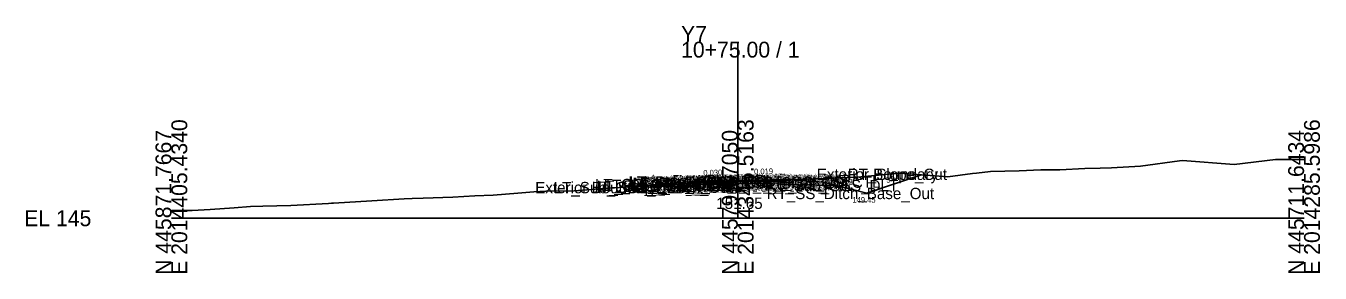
# Model space of a CAD drawing. Extents: x -26 to 203, y -10 to 7527.
# Drawn here: x -25.7 to 202.8, y 1490.3 to 1534 of the extents above; entities that cross this region are included whole.
import ezdxf

# ---------------------------------------------------------------- set-up
doc = ezdxf.new("R2010")
doc.units = 0
for name, color, linetype in [('Exist CMT Pavement', 7, 'Continuous'), ('Exist Cross Section Cell', 7, 'Continuous'), ('Exist XS Center Line Elevation Label', 7, 'Continuous'), ('Exist XS Ground Line', 7, 'Continuous'), ('Prop CMT Pvmt Course 1', 7, 'Continuous'), ('Prop CMT Pvmt Course 1 Wedge', 7, 'Continuous'), ('Prop CMT Pvmt Course 2', 7, 'Continuous'), ('Prop CMT Pvmt Course 2 Wedge', 7, 'Continuous'), ('Prop CMT Pvmt Course 3', 7, 'Continuous'), ('Prop CMT Pvmt Course 3 Wedge', 7, 'Continuous'), ('Prop CMT Pvmt Surface', 7, 'Continuous'), ('Prop CMT Pvmt Surface Shoulder', 7, 'Continuous'), ('Prop CMT Pvmt Wedge Surface 1', 7, 'Continuous'), ('Prop CMT Pvmt Wedge Surface 2', 7, 'Continuous'), ('Prop CMT Pvmt Wedge Surface 3', 7, 'Continuous'), ('Prop CMT Shld Paved Course 1', 7, 'Continuous'), ('Prop CMT Shld Paved Course 2', 7, 'Continuous'), ('Prop CMT Shld Paved Course 3', 7, 'Continuous'), ('Prop CMT Slope Grass', 7, 'Continuous'), ('Prop CMT Subgrade Earthwork', 7, 'Continuous'), ('Prop XS Ditch Standard Text', 7, 'Continuous'), ('Prop XS Earthwork Shape', 7, 'Continuous'), ('Prop XS SE Text', 7, 'Continuous'), ('Prop XS Side Slope Text', 7, 'Continuous'), ('Scratch_Level_0', 7, 'Continuous')]:
    doc.layers.add(name, color=color, linetype=linetype)

msp = doc.modelspace()

# ---------------------------------------------------------------- linework, layer by layer
at = {"layer": 'Exist CMT Pavement'}
msp.add_lwpolyline([(93.34, 1506.4), (94.16, 1506.44), (100, 1506.65), (101.02, 1506.69), (101.74, 1506.69), (107.53, 1506.71)], dxfattribs=at)
at = {"layer": 'Exist Cross Section Cell'}
for p, q in [((100, 1500), (100, 1531.19)), ((0, 1500), (100, 1500)), ((100, 1500), (200, 1500))]:
    msp.add_line(p, q, dxfattribs=at)
at = {"layer": 'Exist XS Ground Line'}
msp.add_lwpolyline([(0, 1501.37), (3.64, 1501.37), (6.82, 1501.53), (11.08, 1501.85), (13.97, 1502.09), (16.13, 1502.15), (21.11, 1502.26), (27.77, 1502.63), (28.26, 1502.66), (28.62, 1502.68), (35.4, 1503.07), (41.11, 1503.42), (42.54, 1503.52), (44.46, 1503.56), (49.69, 1503.7), (53.6, 1503.94), (56.83, 1504.1), (61.15, 1504.46), (63.98, 1504.65), (66.09, 1504.77), (71.12, 1504.87), (77.84, 1505.37), (78.27, 1505.38), (79.84, 1505.49), (90.97, 1506.09), (93.34, 1506.4), (94.16, 1506.44), (100, 1506.65), (101.02, 1506.69), (101.74, 1506.69), (107.53, 1506.71), (108.47, 1506.86), (112, 1506.89), (121.14, 1507.27), (127.92, 1507.91), (128.55, 1507.94), (137.08, 1507.31), (141.47, 1507.88), (142.19, 1507.95), (144.61, 1508.25), (149.72, 1508.37), (153.54, 1508.58), (156.86, 1508.58), (161.3, 1508.8), (164.01, 1508.84), (166.03, 1508.88), (171.15, 1509.2), (177.99, 1510.15), (178.52, 1510.19), (187.64, 1509.52), (194.94, 1510.4), (200, 1510.37)], dxfattribs=at)
at = {"layer": 'Prop CMT Pvmt Course 1'}
for points in [[(100, 1506.69), (91.43, 1506.44)], [(91.43, 1506.44), (91.43, 1506.19)], [(91.43, 1506.19), (93.34, 1506.24)], [(93.34, 1506.37), (100, 1506.57)], [(93.34, 1506.24), (93.34, 1506.37)], [(100, 1506.69), (109.07, 1506.86)], [(107.53, 1506.71), (100, 1506.57)], [(100, 1506.44), (100, 1506.69)], [(100, 1506.44), (100, 1506.69)], [(100, 1506.57), (100, 1506.44), (100, 1506.44)], [(100, 1506.57), (100, 1506.44), (100, 1506.44)], [(107.53, 1506.58), (107.53, 1506.71)], [(109.07, 1506.61), (107.53, 1506.58)], [(109.07, 1506.86), (109.07, 1506.61)]]:
    msp.add_lwpolyline(points, dxfattribs=at)
at = {"layer": 'Prop CMT Pvmt Course 1 Wedge'}
for points in [[(100, 1506.57), (93.34, 1506.37)], [(100, 1506.57), (107.53, 1506.71)]]:
    msp.add_lwpolyline(points, dxfattribs=at)
at = {"layer": 'Prop CMT Pvmt Course 2'}
for points in [[(93.34, 1506.24), (91.43, 1506.19)], [(91.43, 1506.19), (91.43, 1505.85)], [(93.34, 1505.91), (93.34, 1506.24)], [(107.53, 1506.58), (109.07, 1506.61)], [(107.53, 1506.25), (107.53, 1506.58)], [(109.07, 1506.28), (107.53, 1506.25)], [(109.07, 1506.61), (109.07, 1506.28)], [(91.43, 1505.85), (93.34, 1505.91)]]:
    msp.add_lwpolyline(points, dxfattribs=at)
at = {"layer": 'Prop CMT Pvmt Course 2 Wedge'}
for points in [[(100, 1506.44), (93.34, 1506.24)], [(100, 1506.44), (107.53, 1506.58)]]:
    msp.add_lwpolyline(points, dxfattribs=at)
at = {"layer": 'Prop CMT Pvmt Course 3'}
for points in [[(107.53, 1506.25), (109.07, 1506.28)], [(107.53, 1505.92), (107.53, 1506.25)], [(109.07, 1506.28), (109.07, 1505.94)], [(93.34, 1505.91), (91.43, 1505.85)], [(91.43, 1505.85), (91.43, 1505.52)], [(91.43, 1505.52), (93.34, 1505.58)], [(93.34, 1505.58), (93.34, 1505.91)], [(109.07, 1505.94), (107.53, 1505.92)]]:
    msp.add_lwpolyline(points, dxfattribs=at)
at = {"layer": 'Prop CMT Pvmt Course 3 Wedge'}
for points in [[(100, 1506.11), (93.34, 1505.91)], [(100, 1506.11), (107.53, 1506.25)]]:
    msp.add_lwpolyline(points, dxfattribs=at)
at = {"layer": 'Prop CMT Pvmt Surface'}
for points in [[(100, 1506.69), (91.43, 1506.44)], [(100, 1506.69), (109.07, 1506.86)]]:
    msp.add_lwpolyline(points, dxfattribs=at)
at = {"layer": 'Prop CMT Pvmt Surface Shoulder'}
for points in [[(91.43, 1506.44), (91.43, 1506.44)], [(109.07, 1506.86), (109.07, 1506.86)]]:
    msp.add_lwpolyline(points, dxfattribs=at)
at = {"layer": 'Prop CMT Pvmt Wedge Surface 1'}
for points in [[(91.43, 1506.19), (91.43, 1506.44)], [(93.34, 1506.24), (91.43, 1506.19)], [(100, 1506.57), (93.34, 1506.37)], [(93.34, 1506.37), (93.34, 1506.24)], [(100, 1506.57), (107.53, 1506.71)], [(107.53, 1506.71), (107.53, 1506.58)], [(107.53, 1506.58), (109.07, 1506.61)], [(109.07, 1506.61), (109.07, 1506.86)]]:
    msp.add_lwpolyline(points, dxfattribs=at)
at = {"layer": 'Prop CMT Pvmt Wedge Surface 2'}
for points in [[(100, 1506.44), (91.43, 1506.19)], [(91.43, 1506.19), (91.43, 1506.44)], [(100, 1506.44), (109.07, 1506.61)], [(109.07, 1506.61), (109.07, 1506.86)]]:
    msp.add_lwpolyline(points, dxfattribs=at)
at = {"layer": 'Prop CMT Pvmt Wedge Surface 3'}
for points in [[(91.43, 1505.85), (91.43, 1506.44)], [(100, 1506.11), (91.43, 1505.85)], [(100, 1506.11), (109.07, 1506.28)], [(109.07, 1506.28), (109.07, 1506.86)]]:
    msp.add_lwpolyline(points, dxfattribs=at)
at = {"layer": 'Prop CMT Shld Paved Course 1'}
for points in [[(91.43, 1506.44), (91.18, 1506.18)], [(91.18, 1506.18), (91.43, 1506.19)], [(91.43, 1506.44), (91.43, 1506.44)], [(91.43, 1506.19), (91.43, 1506.44)], [(109.07, 1506.86), (109.07, 1506.86)], [(109.07, 1506.86), (109.33, 1506.61)], [(109.07, 1506.61), (109.07, 1506.86)], [(109.33, 1506.61), (109.07, 1506.61)]]:
    msp.add_lwpolyline(points, dxfattribs=at)
at = {"layer": 'Prop CMT Shld Paved Course 2'}
for points in [[(91.43, 1506.19), (91.18, 1506.18), (90.84, 1505.84)], [(91.43, 1505.85), (91.43, 1506.19)], [(109.07, 1506.61), (109.33, 1506.61), (109.67, 1506.27)], [(109.07, 1506.28), (109.07, 1506.61)], [(109.67, 1506.27), (109.07, 1506.28)], [(90.84, 1505.84), (91.43, 1505.85)]]:
    msp.add_lwpolyline(points, dxfattribs=at)
at = {"layer": 'Prop CMT Shld Paved Course 3'}
for points in [[(109.07, 1506.28), (109.17, 1506.28), (109.67, 1506.27), (110.01, 1505.93)], [(109.07, 1505.94), (109.07, 1506.28)], [(90, 1505.49), (91.43, 1505.52)], [(91.43, 1505.85), (90.84, 1505.84), (90.5, 1505.5)], [(91.43, 1505.52), (91.43, 1505.85)], [(110.51, 1505.92), (109.07, 1505.94)]]:
    msp.add_lwpolyline(points, dxfattribs=at)
at = {"layer": 'Prop CMT Slope Grass'}
for points in [[(91.43, 1506.44), (85.43, 1505.96), (84.85, 1505.76)], [(109.07, 1506.86), (115.07, 1506.38), (122.79, 1504.45)], [(122.79, 1504.45), (132.4, 1507.66)]]:
    msp.add_lwpolyline(points, dxfattribs=at)
at = {"layer": 'Prop CMT Subgrade Earthwork'}
msp.add_line((90, 1505.49), (84.85, 1505.76), dxfattribs=at)
for points in [[(93.34, 1505.58), (93.34, 1506.4)], [(107.53, 1505.92), (107.53, 1506.71)], [(91.43, 1505.52), (90, 1505.49)], [(93.34, 1505.58), (91.43, 1505.52)], [(107.53, 1505.92), (109.07, 1505.94)], [(109.07, 1505.94), (110.51, 1505.92)], [(110.51, 1505.92), (117.49, 1505.78)]]:
    msp.add_lwpolyline(points, dxfattribs=at)
at = {"layer": 'Prop XS Earthwork Shape'}
for points in [[(84.85, 1505.76), (90.97, 1506.09), (93.34, 1506.4), (93.34, 1505.58), (91.43, 1505.52), (90, 1505.49)], [(108.43, 1506.85), (109.07, 1506.86), (115.07, 1506.38), (117.49, 1505.78), (110.51, 1505.92), (109.07, 1505.94), (107.53, 1505.92), (107.53, 1506.71)], [(108.43, 1506.85), (108.47, 1506.86), (112, 1506.89), (121.14, 1507.27), (127.92, 1507.91), (128.55, 1507.94), (132.4, 1507.66), (122.79, 1504.45), (117.49, 1505.78), (115.07, 1506.38), (109.07, 1506.86)]]:
    msp.add_lwpolyline(points, close=True, dxfattribs=at)

# ---------------------------------------------------------------- texts
at = {"layer": 'Exist Cross Section Cell'}
for s, p in [('Y7', (90, 1531.19)), ('10+75.00 / 1', (90, 1528.39)), ('EL 145', (-26, 1498.6))]:
    msp.add_text(s, height=2.8, dxfattribs=at).set_placement(p)
for s, p in [('N 445871.7667', (0, 1490)), ('E 2014405.4340', (2.8, 1490)), ('N 445791.7050', (100, 1490)), ('E 2014345.5163', (102.8, 1490)), ('N 445711.6434', (200, 1490)), ('E 2014285.5986', (202.8, 1490))]:
    msp.add_text(s, height=2.8, rotation=90, dxfattribs=at).set_placement(p)
at = {"layer": 'Exist XS Center Line Elevation Label'}
msp.add_text('151.65', height=2, dxfattribs=at).set_placement((96.22, 1501.65))
at = {"layer": 'Prop XS Ditch Standard Text'}
msp.add_text('149.45', height=1, dxfattribs=at).set_placement((120.25, 1502.74))
at = {"layer": 'Prop XS SE Text'}
for s, rotation, p in [('0.030', 1.7184, (93.94, 1507.51)), ('0.019', 1.0645, (102.9, 1507.75))]:
    msp.add_text(s, height=1, rotation=rotation, dxfattribs=at).set_placement(p)
at = {"layer": 'Prop XS Side Slope Text'}
for s, rotation, p in [('3:1', 18.4332, (84.01, 1506.27)), ('4:1', 345.9638, (118.49, 1506.3)), ('3:1', 18.4349, (126.35, 1506.18))]:
    msp.add_text(s, height=1, rotation=rotation, dxfattribs=at).set_placement(p)
at = {"layer": 'Scratch_Level_0'}
for s, p in [('Exterior Boundary', (113.97, 1506.76)), ('RT_Slope_Cut', (119.42, 1506.76)), ('Exterior Boundary', (64.25, 1504.42)), ('LT_Sub_OSS_DLT', (67.51, 1504.42)), ('LT_Sub_Trench_Out', (74.2, 1504.49)), ('LT_GS_OS_CTL', (74.8, 1504.96)), ('LT_Slope_Fill', (75.09, 1504.67)), ('LT_PS3_Shelf_Out', (76.32, 1504.83)), ('LT_Sub Tie Out', (80.68, 1505.4)), ('LT_PV_OEEOP_EG', (80.89, 1505.4)), ('LT_PS3_OEOP', (81.08, 1504.84)), ('LT_PS2_OEOP', (81.42, 1505.18)), ('LT_Sub_OEOT', (81.51, 1504.52)), ('LT_PV2_OEOT', (81.61, 1505.19)), ('LT_PV3_OEOT', (81.61, 1504.85)), ('LT_PV1_OEOT', (82.17, 1505.44)), ('LT_PS1_OEOP', (82.24, 1505.44)), ('LT_Sub_OEEOP', (82.55, 1504.58)), ('LT_PV2_OEEOP', (82.65, 1505.24)), ('LT_PV3_OEEOP', (82.65, 1504.91)), ('LT_PV1_OEEOP', (83.22, 1505.37)), ('RT_PV_IEEOP_EG', (88.14, 1505.65)), ('LT_PV_IEEOP_EG', (88.19, 1505.65)), ('RT_PV2_IEEOP', (89.91, 1505.44)), ('RT_PV3_IEEOP', (89.91, 1505.11)), ('LT_PV2_IEEOP', (89.95, 1505.44)), ('LT_PV3_IEEOP', (89.95, 1505.11)), ('RT_PV1_IEEOP', (90.47, 1505.57)), ('LT_PV1_IEEOP', (90.52, 1505.57)), ('PV2_PGL', (93.91, 1505.44)), ('PV1_PGL', (94.47, 1505.69)), ('RT_Sub_Trench_Out', (94.67, 1504.92)), ('RT_Sub Tie Out', (94.82, 1505.71)), ('RT_PV_OEEOP_EG', (95.03, 1505.71)), ('RT_PS3_Shelf_Out', (96.1, 1505.26)), ('RT_Sub_OEEOP', (96.7, 1504.92)), ('RT_PV2_OEEOP', (96.79, 1505.58)), ('RT_PV3_OEEOP', (96.79, 1505.25)), ('RT_PV1_OEEOP', (97.36, 1505.71)), ('RT_Sub_OEOT', (99.1, 1504.94)), ('RT_PV2_OEOT', (99.2, 1505.61)), ('RT_PV3_OEOT', (99.2, 1505.28)), ('RT_PS2_OEOP', (99.52, 1505.61)), ('RT_PV1_OEOT', (99.77, 1505.86)), ('RT_PS1_OEOP', (99.83, 1505.86)), ('RT_PS3_OEOP', (99.86, 1505.27)), ('RT_GS_OS_CTL', (104.4, 1505.38)), ('RT_Sub_OSS_DLT', (104.85, 1504.78)), ('RT_SS_Ditch_Base_Out', (105.1, 1503.38))]:
    msp.add_text(s, height=2, dxfattribs=at).set_placement(p)

doc.saveas('drawing.dxf')
